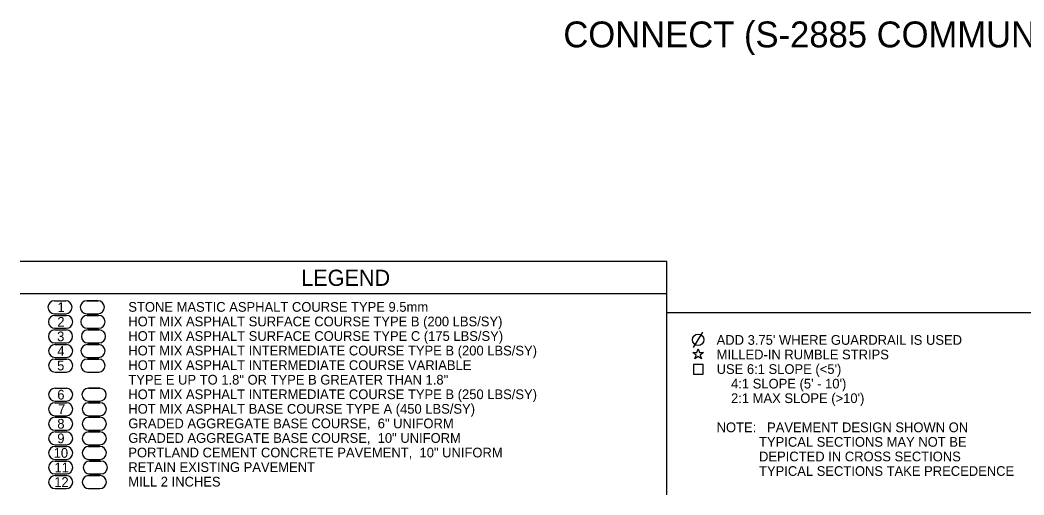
# Model space of a CAD drawing. Extents: x 2003207 to 2014043, y 843846 to 860154.
# Drawn here: x 2013805.7 to 2013867.8, y 844806 to 844835.3 of the extents above; entities that cross this region are included whole.
import ezdxf

# ---------------------------------------------------------------- set-up
doc = ezdxf.new("R2010")
doc.units = 0
for name, color, linetype in [('RD_EX_Road', 7, 'Continuous'), ('RD_EX_Road_txCode', 7, 'Continuous'), ('RD_QTY_ConcPave', 7, 'Continuous'), ('RD_QTY_Intermediate', 7, 'Continuous'), ('RD_QTY_Milling', 7, 'Continuous'), ('RD_QTY_Surf_Course', 7, 'Continuous'), ('RD_SHT_Bndy', 7, 'Continuous'), ('RD_TX_Misc2', 7, 'Continuous')]:
    doc.layers.add(name, color=color, linetype=linetype)

msp = doc.modelspace()

# ---------------------------------------------------------------- linework, layer by layer
at = {"layer": 'RD_EX_Road'}
for p, q in [((2013810.723, 844808.087), (2013810.023, 844808.087)), ((2013810.661, 844807.187), (2013809.961, 844807.187)), ((2013810.023, 844807.287), (2013810.723, 844807.287)), ((2013809.961, 844806.387), (2013810.661, 844806.387))]:
    msp.add_line(p, q, dxfattribs=at)
for centre, start, end in [((2013810.023, 844807.687), 90, 270), ((2013810.723, 844807.687), 270, 90), ((2013809.961, 844806.787), 90, 270), ((2013810.661, 844806.787), 270, 90)]:
    msp.add_arc(centre, 0.4, start, end, dxfattribs=at)
at = {"layer": 'RD_EX_Road_txCode'}
msp.add_line((2013847.384, 844815.107), (2013847.95, 844816.05), dxfattribs=at)
for points in [[(2013847.335, 844814.786), (2013847.589, 844814.786), (2013847.667, 844815.028), (2013847.746, 844814.786), (2013848, 844814.786), (2013847.795, 844814.637), (2013847.873, 844814.395), (2013847.667, 844814.544), (2013847.462, 844814.395), (2013847.54, 844814.637)], [(2013847.367, 844813.452), (2013847.967, 844813.452), (2013847.967, 844814.052), (2013847.367, 844814.052)]]:
    msp.add_lwpolyline(points, close=True, dxfattribs=at)
msp.add_circle((2013847.667, 844815.578), 0.35, dxfattribs=at)
at = {"layer": 'RD_QTY_ConcPave'}
for p, q in [((2013810.661, 844810.787), (2013809.961, 844810.787)), ((2013809.961, 844809.987), (2013810.661, 844809.987)), ((2013810.661, 844809.887), (2013809.961, 844809.887)), ((2013809.961, 844809.087), (2013810.661, 844809.087)), ((2013810.661, 844808.987), (2013809.961, 844808.987)), ((2013809.961, 844808.187), (2013810.661, 844808.187))]:
    msp.add_line(p, q, dxfattribs=at)
for centre, start, end in [((2013809.961, 844810.387), 90, 270), ((2013810.661, 844810.387), 270, 90), ((2013809.961, 844809.487), 90, 270), ((2013810.661, 844809.487), 270, 90), ((2013809.961, 844808.587), 90, 270), ((2013810.661, 844808.587), 270, 90)]:
    msp.add_arc(centre, 0.4, start, end, dxfattribs=at)
at = {"layer": 'RD_QTY_Intermediate'}
for p, q in [((2013810.582, 844815.287), (2013809.882, 844815.287)), ((2013809.882, 844814.487), (2013810.582, 844814.487)), ((2013810.582, 844814.387), (2013809.882, 844814.387)), ((2013809.882, 844813.587), (2013810.582, 844813.587)), ((2013810.65, 844812.587), (2013809.95, 844812.587)), ((2013809.95, 844811.787), (2013810.65, 844811.787)), ((2013810.661, 844811.687), (2013809.961, 844811.687)), ((2013809.961, 844810.887), (2013810.661, 844810.887))]:
    msp.add_line(p, q, dxfattribs=at)
for centre, start, end in [((2013809.882, 844814.887), 90, 270), ((2013810.582, 844814.887), 270, 90), ((2013809.882, 844813.987), 90, 270), ((2013810.582, 844813.987), 270, 90), ((2013809.95, 844812.187), 90, 270), ((2013810.65, 844812.187), 270, 90), ((2013809.961, 844811.287), 90, 270), ((2013810.661, 844811.287), 270, 90)]:
    msp.add_arc(centre, 0.4, start, end, dxfattribs=at)
at = {"layer": 'RD_QTY_Milling'}
for p, q in [((2013810.661, 844807.187), (2013809.961, 844807.187)), ((2013809.961, 844806.387), (2013810.661, 844806.387))]:
    msp.add_line(p, q, dxfattribs=at)
for centre, start, end in [((2013809.961, 844806.787), 90, 270), ((2013810.661, 844806.787), 270, 90)]:
    msp.add_arc(centre, 0.4, start, end, dxfattribs=at)
at = {"layer": 'RD_QTY_Surf_Course'}
for p, q in [((2013810.542, 844817.987), (2013809.842, 844817.987)), ((2013809.842, 844817.187), (2013810.542, 844817.187)), ((2013810.576, 844817.087), (2013809.876, 844817.087)), ((2013809.876, 844816.287), (2013810.576, 844816.287)), ((2013810.61, 844816.187), (2013809.91, 844816.187)), ((2013809.91, 844815.387), (2013810.61, 844815.387))]:
    msp.add_line(p, q, dxfattribs=at)
for centre, start, end in [((2013809.842, 844817.587), 90, 270), ((2013810.542, 844817.587), 270, 90), ((2013809.876, 844816.687), 90, 270), ((2013810.576, 844816.687), 270, 90), ((2013809.91, 844815.787), 90, 270), ((2013810.61, 844815.787), 270, 90)]:
    msp.add_arc(centre, 0.4, start, end, dxfattribs=at)
at = {"layer": 'RD_SHT_Bndy'}
for p, q in [((2013845.721, 844820.41), (2013805.721, 844820.41)), ((2013845.721, 844818.41), (2013845.721, 844820.41)), ((2013845.721, 844818.41), (2013805.721, 844818.41)), ((2013845.721, 844805.992), (2013845.721, 844818.41)), ((2013868.755, 844817.242), (2013845.755, 844817.242))]:
    msp.add_line(p, q, dxfattribs=at)
at = {"layer": 'RD_TX_Misc2'}
for p, q in [((2013807.842, 844817.987), (2013808.542, 844817.987)), ((2013809.842, 844817.987), (2013810.542, 844817.987)), ((2013807.842, 844817.187), (2013808.542, 844817.187)), ((2013807.876, 844817.087), (2013808.576, 844817.087)), ((2013809.842, 844817.187), (2013810.542, 844817.187)), ((2013809.876, 844817.087), (2013810.576, 844817.087)), ((2013807.871, 844816.187), (2013808.571, 844816.187)), ((2013807.876, 844816.287), (2013808.576, 844816.287)), ((2013809.876, 844816.287), (2013810.576, 844816.287)), ((2013809.91, 844816.187), (2013810.61, 844816.187)), ((2013807.871, 844815.387), (2013808.571, 844815.387)), ((2013807.882, 844815.287), (2013808.582, 844815.287)), ((2013809.882, 844815.287), (2013810.582, 844815.287)), ((2013809.91, 844815.387), (2013810.61, 844815.387)), ((2013807.882, 844814.487), (2013808.582, 844814.487)), ((2013807.882, 844814.387), (2013808.582, 844814.387)), ((2013809.882, 844814.487), (2013810.582, 844814.487)), ((2013809.882, 844814.387), (2013810.582, 844814.387)), ((2013807.882, 844813.587), (2013808.582, 844813.587)), ((2013809.882, 844813.587), (2013810.582, 844813.587)), ((2013807.882, 844812.587), (2013808.582, 844812.587)), ((2013809.95, 844812.587), (2013810.65, 844812.587)), ((2013807.882, 844811.787), (2013808.582, 844811.787)), ((2013807.882, 844811.687), (2013808.582, 844811.687)), ((2013809.95, 844811.787), (2013810.65, 844811.787)), ((2013809.961, 844811.687), (2013810.661, 844811.687)), ((2013807.882, 844810.887), (2013808.582, 844810.887)), ((2013807.882, 844810.787), (2013808.582, 844810.787)), ((2013809.961, 844810.887), (2013810.661, 844810.887)), ((2013809.961, 844810.787), (2013810.661, 844810.787)), ((2013807.882, 844809.987), (2013808.582, 844809.987)), ((2013807.882, 844809.887), (2013808.582, 844809.887)), ((2013809.961, 844809.987), (2013810.661, 844809.987)), ((2013809.961, 844809.887), (2013810.661, 844809.887)), ((2013807.882, 844809.087), (2013808.582, 844809.087)), ((2013807.882, 844808.987), (2013808.582, 844808.987)), ((2013809.961, 844809.087), (2013810.661, 844809.087)), ((2013809.961, 844808.987), (2013810.661, 844808.987)), ((2013807.882, 844808.187), (2013808.582, 844808.187)), ((2013807.882, 844808.087), (2013808.582, 844808.087)), ((2013809.961, 844808.187), (2013810.661, 844808.187)), ((2013810.023, 844808.087), (2013810.723, 844808.087)), ((2013807.882, 844807.287), (2013808.582, 844807.287)), ((2013807.882, 844807.187), (2013808.582, 844807.187)), ((2013809.961, 844807.187), (2013810.661, 844807.187)), ((2013810.023, 844807.287), (2013810.723, 844807.287)), ((2013807.882, 844806.387), (2013808.582, 844806.387)), ((2013809.961, 844806.387), (2013810.661, 844806.387))]:
    msp.add_line(p, q, dxfattribs=at)
for centre, start, end in [((2013807.842, 844817.587), 90, 270), ((2013808.542, 844817.587), 270, 90), ((2013809.842, 844817.587), 90, 270), ((2013810.542, 844817.587), 270, 90), ((2013807.876, 844816.687), 90, 270), ((2013808.576, 844816.687), 270, 90), ((2013809.876, 844816.687), 90, 270), ((2013810.576, 844816.687), 270, 90), ((2013807.871, 844815.787), 90, 270), ((2013808.571, 844815.787), 270, 90), ((2013809.91, 844815.787), 90, 270), ((2013810.61, 844815.787), 270, 90), ((2013807.882, 844814.887), 90, 270), ((2013808.582, 844814.887), 270, 90), ((2013809.882, 844814.887), 90, 270), ((2013810.582, 844814.887), 270, 90), ((2013807.882, 844813.987), 90, 270), ((2013808.582, 844813.987), 270, 90), ((2013809.882, 844813.987), 90, 270), ((2013810.582, 844813.987), 270, 90), ((2013807.882, 844812.187), 90, 270), ((2013808.582, 844812.187), 270, 90), ((2013809.95, 844812.187), 90, 270), ((2013810.65, 844812.187), 270, 90), ((2013807.882, 844811.287), 90, 270), ((2013808.582, 844811.287), 270, 90), ((2013809.961, 844811.287), 90, 270), ((2013810.661, 844811.287), 270, 90), ((2013807.882, 844810.387), 90, 270), ((2013808.582, 844810.387), 270, 90), ((2013809.961, 844810.387), 90, 270), ((2013810.661, 844810.387), 270, 90), ((2013807.882, 844809.487), 90, 270), ((2013808.582, 844809.487), 270, 90), ((2013809.961, 844809.487), 90, 270), ((2013810.661, 844809.487), 270, 90), ((2013807.882, 844808.587), 90, 270), ((2013808.582, 844808.587), 270, 90), ((2013809.961, 844808.587), 90, 270), ((2013810.661, 844808.587), 270, 90), ((2013807.882, 844807.687), 90, 270), ((2013808.582, 844807.687), 270, 90), ((2013810.023, 844807.687), 90, 270), ((2013810.723, 844807.687), 270, 90), ((2013807.882, 844806.787), 90, 270), ((2013808.582, 844806.787), 270, 90), ((2013809.961, 844806.787), 90, 270), ((2013810.661, 844806.787), 270, 90)]:
    msp.add_arc(centre, 0.4, start, end, dxfattribs=at)

# ---------------------------------------------------------------- texts
at = {"layer": 'RD_EX_Road_txCode'}
for s, height, p in [('CONNECT (S-2885 COMMUNITY ROAD) STA. 113+50.00 TO STA. 117+54.21', 1.6, (2013839.325, 844833.649)), ('LEGEND', 1, (2013823.11, 844818.91)), ('STONE MASTIC ASPHALT COURSE TYPE 9.5mm', 0.6, (2013812.417, 844817.31)), ('HOT MIX ASPHALT SURFACE COURSE TYPE B (200 LBS/SY)', 0.6, (2013812.417, 844816.41)), ('HOT MIX ASPHALT SURFACE COURSE TYPE C (175 LBS/SY)', 0.6, (2013812.417, 844815.51)), ("ADD 3.75' WHERE GUARDRAIL IS USED", 0.6, (2013848.808, 844815.268)), ('HOT MIX ASPHALT INTERMEDIATE COURSE TYPE B (200 LBS/SY)', 0.6, (2013812.417, 844814.61)), ('MILLED-IN RUMBLE STRIPS', 0.6, (2013848.808, 844814.368)), ('HOT MIX ASPHALT INTERMEDIATE COURSE VARIABLE ', 0.6, (2013812.417, 844813.71)), ("USE 6:1 SLOPE (<5')", 0.6, (2013848.808, 844813.468)), ('TYPE E UP TO 1.8" OR TYPE B GREATER THAN 1.8"', 0.6, (2013812.417, 844812.81)), ("    4:1 SLOPE (5' - 10')", 0.6, (2013848.808, 844812.568)), ('HOT MIX ASPHALT INTERMEDIATE COURSE TYPE B (250 LBS/SY)', 0.6, (2013812.417, 844811.91)), ("    2:1 MAX SLOPE (>10')", 0.6, (2013848.808, 844811.668)), ('HOT MIX ASPHALT BASE COURSE TYPE A (450 LBS/SY)', 0.6, (2013812.417, 844811.01)), ('GRADED AGGREGATE BASE COURSE,  6" UNIFORM', 0.6, (2013812.417, 844810.11)), ('NOTE:   PAVEMENT DESIGN SHOWN ON', 0.6, (2013848.808, 844809.868)), ('GRADED AGGREGATE BASE COURSE,  10" UNIFORM', 0.6, (2013812.417, 844809.21)), (' TYPICAL SECTIONS MAY NOT BE ', 0.6, (2013851.208, 844808.968)), ('PORTLAND CEMENT CONCRETE PAVEMENT,  10" UNIFORM', 0.6, (2013812.417, 844808.31)), (' DEPICTED IN CROSS SECTIONS', 0.6, (2013851.208, 844808.068)), ('RETAIN EXISTING PAVEMENT', 0.6, (2013812.417, 844807.41)), (' TYPICAL SECTIONS TAKE PRECEDENCE', 0.6, (2013851.208, 844807.168)), ('MILL 2 INCHES', 0.6, (2013812.417, 844806.51))]:
    msp.add_text(s, height=height, dxfattribs=at).set_placement(p)
at = {"layer": 'RD_TX_Misc2'}
for s, p in [('1', (2013808.039, 844817.287)), ('2', (2013808.022, 844816.387)), ('3', (2013808.011, 844815.487)), ('4', (2013808.023, 844814.587)), ('5', (2013808.011, 844813.687)), ('6', (2013808.023, 844811.887)), ('7 ', (2013808.066, 844810.987)), ('8', (2013808.023, 844810.087)), ('9', (2013808.023, 844809.187)), ('10', (2013807.796, 844808.287)), ('11', (2013807.852, 844807.387)), ('12', (2013807.835, 844806.487))]:
    msp.add_text(s, height=0.6, dxfattribs=at).set_placement(p)

doc.saveas('drawing.dxf')
